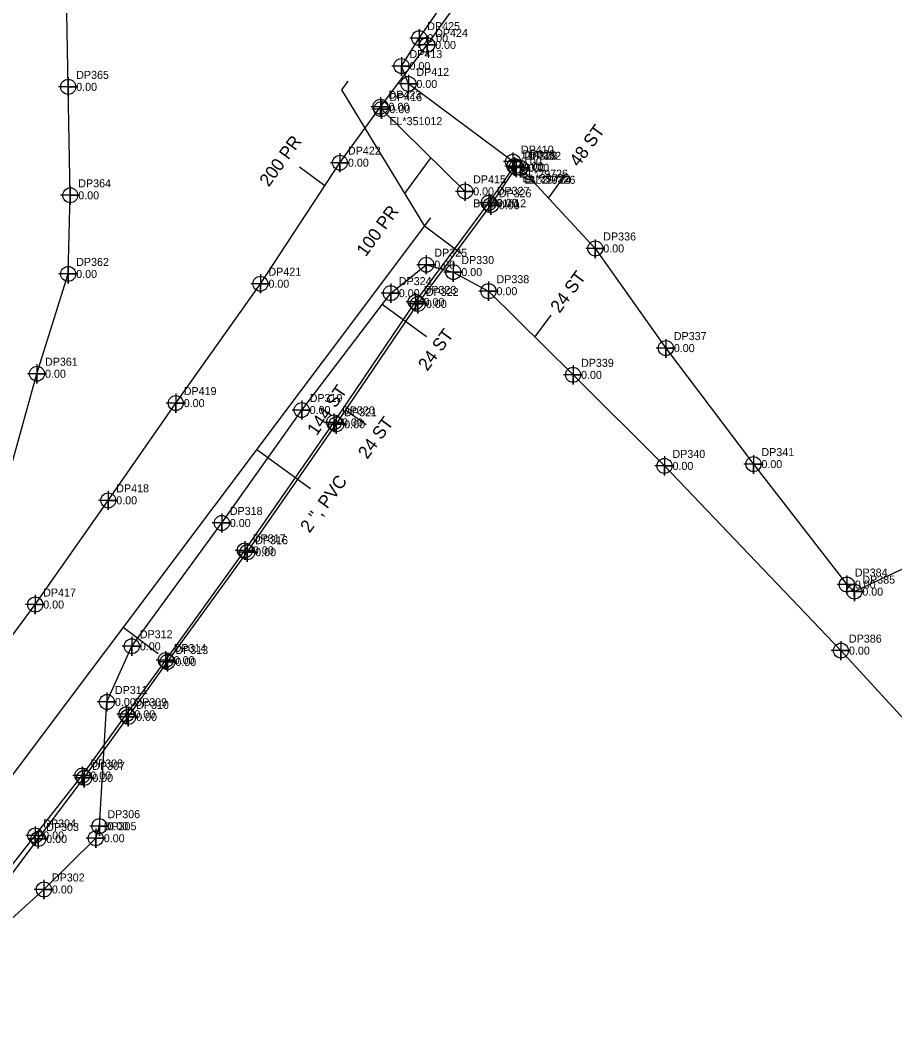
# Model space of a CAD drawing. Extents: x 1182504 to 1186036, y 573002 to 575111.
# Drawn here: x 1183867 to 1184140, y 573034.4 to 573350.5 of the extents above; entities that cross this region are included whole.
import ezdxf

# ---------------------------------------------------------------- set-up
doc = ezdxf.new("R2010")
doc.units = 0
for name, color, linetype in [('Exist Utilities Telephone UG Cable SUE LOS C', 7, 'Continuous'), ('Exist Utilities Telephone UG Cable SUE LOS C Cogo Comment', 7, 'Continuous'), ('Exist Utilities Telephone UG Cable SUE LOS C Cogo Elevation', 7, 'Continuous'), ('Exist Utilities Telephone UG Cable SUE LOS C Cogo Number', 7, 'Continuous'), ('Exist Utilities Telephone UG Cable SUE LOS C Cogo Point CELL', 7, 'Continuous'), ('Exist Utilities Telephone UG Cable SUE LOS C Leader', 7, 'Continuous'), ('Exist Utilities Telephone UG Cable SUE LOS C Text', 7, 'Continuous'), ('Exist Utilities Telephone UG Conduit SUE LOS B', 7, 'Continuous'), ('Exist Utilities Telephone UG Conduit SUE LOS B Cogo Comment', 7, 'Continuous'), ('Exist Utilities Telephone UG Conduit SUE LOS B Cogo Elevation', 7, 'Continuous'), ('Exist Utilities Telephone UG Conduit SUE LOS B Cogo Number', 7, 'Continuous'), ('Exist Utilities Telephone UG Conduit SUE LOS B Cogo Point CELL', 7, 'Continuous'), ('Exist Utilities Telephone UG Conduit SUE LOS B Leader', 7, 'Continuous'), ('Exist Utilities Telephone UG Conduit SUE LOS B Text', 7, 'Continuous'), ('Exist Utilities Telephone UG FO SUE LOS C', 7, 'Continuous'), ('Exist Utilities Telephone UG FO SUE LOS C Cogo Elevation', 7, 'Continuous'), ('Exist Utilities Telephone UG FO SUE LOS C Cogo Number', 7, 'Continuous'), ('Exist Utilities Telephone UG FO SUE LOS C Cogo Point CELL', 7, 'Continuous'), ('Exist Utilities Telephone UG FO SUE LOS C Leader', 7, 'Continuous'), ('Exist Utilities Telephone UG FO SUE LOS C Text', 7, 'Continuous'), ('Exist Utilities Water UG Line SUE LOS C', 7, 'Continuous'), ('Exist Utilities Water UG Line SUE LOS C Leader', 7, 'Continuous'), ('Exist Utilities Water UG Line SUE LOS C Text', 7, 'Continuous')]:
    doc.layers.add(name, color=color, linetype=linetype)

msp = doc.modelspace()

# ---------------------------------------------------------------- linework, layer by layer
at = {"layer": 'Exist Utilities Telephone UG Cable SUE LOS C'}
msp.add_line((1184005.86, 573297.12), (1183979.7, 573322.79), dxfattribs=at)
msp.add_lwpolyline([(1183761.25, 573038.53), (1183769.09, 573034.41), (1183772.83, 573037.9), (1183792.84, 573062.44), (1183815.5, 573091.52), (1183842.15, 573128.3), (1183871.65, 573168.11), (1183894.45, 573200.64), (1183915.52, 573231.01), (1183941.95, 573268.28), (1183966.78, 573306.07), (1183979.43, 573323.54), (1183993.99, 573342.83), (1184020.65, 573379.96), (1184047.47, 573417.15), (1184074.68, 573455.3), (1184101.33, 573490.9), (1184089.43, 573505.28)], dxfattribs=at)
at = {"layer": 'Exist Utilities Telephone UG Cable SUE LOS C Cogo Point CELL'}
for points in [[(1183993.99, 573345.83), (1183993.99, 573339.83), (1183993.99, 573342.83), (1183996.99, 573342.83), (1183990.99, 573342.83)], [(1183979.43, 573326.54), (1183979.43, 573320.54), (1183979.43, 573323.54), (1183982.43, 573323.54), (1183976.43, 573323.54)], [(1183979.7, 573325.79), (1183979.7, 573319.79), (1183979.7, 573322.79), (1183982.7, 573322.79), (1183976.7, 573322.79)], [(1183966.78, 573309.07), (1183966.78, 573303.07), (1183966.78, 573306.07), (1183969.78, 573306.07), (1183963.78, 573306.07)], [(1184005.86, 573300.12), (1184005.86, 573294.12), (1184005.86, 573297.12), (1184008.86, 573297.12), (1184002.86, 573297.12)], [(1183941.95, 573271.28), (1183941.95, 573265.28), (1183941.95, 573268.28), (1183944.95, 573268.28), (1183938.95, 573268.28)], [(1183915.52, 573234.01), (1183915.52, 573228.01), (1183915.52, 573231.01), (1183918.52, 573231.01), (1183912.52, 573231.01)], [(1183894.45, 573203.64), (1183894.45, 573197.64), (1183894.45, 573200.64), (1183897.45, 573200.64), (1183891.45, 573200.64)], [(1183871.65, 573171.11), (1183871.65, 573165.11), (1183871.65, 573168.11), (1183874.65, 573168.11), (1183868.65, 573168.11)]]:
    msp.add_lwpolyline(points, dxfattribs=at)
for centre in [(1183993.99, 573342.83), (1183979.43, 573323.54), (1183979.7, 573322.79), (1183966.78, 573306.07), (1184005.86, 573297.12), (1183941.95, 573268.28), (1183915.52, 573231.01), (1183894.45, 573200.64), (1183871.65, 573168.11)]:
    msp.add_circle(centre, 2.34, dxfattribs=at)
at = {"layer": 'Exist Utilities Telephone UG Cable SUE LOS C Leader'}
for p, q in [((1183995.14, 573307.64), (1183986.97, 573296.43)), ((1183962.06, 573298.88), (1183954.13, 573304.66))]:
    msp.add_line(p, q, dxfattribs=at)
at = {"layer": 'Exist Utilities Telephone UG Conduit SUE LOS B'}
for points in [[(1184020.78, 573306.4), (1183988.14, 573330.66), (1183985.98, 573336.24), (1183991.53, 573344.95), (1184017.37, 573382.34), (1184043.22, 573419.6), (1184071.03, 573458.88), (1184092.18, 573492.71), (1184101.38, 573521.29), (1184118.41, 573555.81), (1184137.37, 573593.76), (1184158.33, 573627.01), (1184186.36, 573674.25), (1184210.73, 573715)], [(1183829.51, 573041.35), (1183847.15, 573064.74), (1183871.66, 573096.02), (1183886.35, 573114.73), (1183900.1, 573133.86), (1183912.38, 573150.76), (1183937.09, 573185.03), (1183964.91, 573224.98), (1183990.4, 573262.6), (1184013.24, 573293.53), (1184021.26, 573304.97)], [(1183829.66, 573040.59), (1183848.87, 573063.35), (1183872.59, 573094.91), (1183886.95, 573113.99), (1183900.66, 573133.04), (1183912.9, 573150.17), (1183937.83, 573184.45), (1183965.61, 573224.4), (1183991.1, 573261.97), (1184013.84, 573292.77), (1184021.83, 573304.52)], [(1184023.09, 573304.47), (1184046.48, 573279.29), (1184068.5, 573248.18), (1184095.84, 573211.96), (1184125, 573174.35), (1184127.35, 573172.14), (1184149.57, 573182.55), (1184175.23, 573190.42), (1184203.21, 573208.51), (1184229.13, 573225.39)]]:
    msp.add_lwpolyline(points, dxfattribs=at)
at = {"layer": 'Exist Utilities Telephone UG Conduit SUE LOS B Cogo Point CELL'}
for points in [[(1183991.51, 573347.76), (1183991.55, 573341.95), (1183991.53, 573344.95), (1183994.55, 573344.95), (1183988.55, 573344.95)], [(1183985.96, 573339.06), (1183985.99, 573333.24), (1183985.98, 573336.24), (1183988.99, 573336.24), (1183982.99, 573336.24)], [(1183988.13, 573333.47), (1183988.16, 573327.66), (1183988.14, 573330.66), (1183991.16, 573330.66), (1183985.16, 573330.66)], [(1184020.76, 573309.22), (1184020.8, 573303.4), (1184020.78, 573306.4), (1184023.8, 573306.4), (1184017.8, 573306.4)], [(1184021.24, 573307.78), (1184021.27, 573301.97), (1184021.26, 573304.97), (1184024.27, 573304.97), (1184018.27, 573304.97)], [(1184021.81, 573307.34), (1184021.84, 573301.52), (1184021.83, 573304.52), (1184024.84, 573304.52), (1184018.84, 573304.52)], [(1184023.08, 573307.29), (1184023.11, 573301.47), (1184023.09, 573304.47), (1184026.11, 573304.47), (1184020.11, 573304.47)], [(1184013.22, 573296.34), (1184013.25, 573290.53), (1184013.24, 573293.53), (1184016.25, 573293.53), (1184010.25, 573293.53)], [(1184013.82, 573295.59), (1184013.86, 573289.77), (1184013.84, 573292.77), (1184016.86, 573292.77), (1184010.86, 573292.77)], [(1184046.46, 573282.1), (1184046.5, 573276.29), (1184046.48, 573279.29), (1184049.5, 573279.29), (1184043.5, 573279.29)], [(1183990.38, 573265.42), (1183990.41, 573259.6), (1183990.4, 573262.6), (1183993.41, 573262.6), (1183987.41, 573262.6)], [(1183991.08, 573264.79), (1183991.11, 573258.97), (1183991.1, 573261.97), (1183994.11, 573261.97), (1183988.11, 573261.97)], [(1184068.49, 573251), (1184068.52, 573245.18), (1184068.5, 573248.18), (1184071.52, 573248.18), (1184065.52, 573248.18)], [(1183964.9, 573227.8), (1183964.93, 573221.98), (1183964.91, 573224.98), (1183967.93, 573224.98), (1183961.93, 573224.98)], [(1183965.6, 573227.21), (1183965.63, 573221.4), (1183965.61, 573224.4), (1183968.63, 573224.4), (1183962.63, 573224.4)], [(1184095.83, 573214.77), (1184095.86, 573208.96), (1184095.84, 573211.96), (1184098.86, 573211.96), (1184092.86, 573211.96)], [(1183937.07, 573187.85), (1183937.11, 573182.03), (1183937.09, 573185.03), (1183940.11, 573185.03), (1183934.11, 573185.03)], [(1183937.81, 573187.27), (1183937.85, 573181.45), (1183937.83, 573184.45), (1183940.85, 573184.45), (1183934.85, 573184.45)], [(1184124.98, 573177.17), (1184125.01, 573171.35), (1184125, 573174.35), (1184128.01, 573174.35), (1184122.01, 573174.35)], [(1184127.33, 573174.95), (1184127.37, 573169.14), (1184127.35, 573172.14), (1184130.37, 573172.14), (1184124.37, 573172.14)], [(1183912.37, 573153.58), (1183912.4, 573147.76), (1183912.38, 573150.76), (1183915.4, 573150.76), (1183909.4, 573150.76)], [(1183912.88, 573152.99), (1183912.91, 573147.17), (1183912.9, 573150.17), (1183915.91, 573150.17), (1183909.91, 573150.17)], [(1183900.08, 573136.67), (1183900.11, 573130.86), (1183900.1, 573133.86), (1183903.11, 573133.86), (1183897.11, 573133.86)], [(1183900.65, 573135.85), (1183900.68, 573130.04), (1183900.66, 573133.04), (1183903.68, 573133.04), (1183897.68, 573133.04)], [(1183886.34, 573117.55), (1183886.37, 573111.73), (1183886.35, 573114.73), (1183889.37, 573114.73), (1183883.37, 573114.73)], [(1183886.93, 573116.81), (1183886.96, 573110.99), (1183886.95, 573113.99), (1183889.96, 573113.99), (1183883.96, 573113.99)], [(1183871.65, 573098.83), (1183871.68, 573093.02), (1183871.66, 573096.02), (1183874.68, 573096.02), (1183868.68, 573096.02)], [(1183872.57, 573097.73), (1183872.6, 573091.91), (1183872.59, 573094.91), (1183875.6, 573094.91), (1183869.6, 573094.91)]]:
    msp.add_lwpolyline(points, dxfattribs=at)
for centre in [(1183991.55, 573344.95), (1183985.99, 573336.24), (1183988.16, 573330.66), (1184020.8, 573306.4), (1184021.27, 573304.97), (1184021.84, 573304.52), (1184023.11, 573304.47), (1184013.25, 573293.53), (1184013.86, 573292.77), (1184046.5, 573279.29), (1183990.41, 573262.6), (1183991.11, 573261.97), (1184068.52, 573248.18), (1183964.93, 573224.98), (1183965.63, 573224.4), (1184095.86, 573211.96), (1183937.11, 573185.03), (1183937.85, 573184.45), (1184125.01, 573174.35), (1184127.37, 573172.14), (1183912.4, 573150.76), (1183912.91, 573150.17), (1183900.11, 573133.86), (1183900.68, 573133.04), (1183886.37, 573114.73), (1183886.96, 573113.99), (1183871.68, 573096.02), (1183872.6, 573094.91)]:
    msp.add_circle(centre, 2.34, dxfattribs=at)
at = {"layer": 'Exist Utilities Telephone UG Conduit SUE LOS B Leader'}
for p, q in [((1184031.9, 573294.99), (1184037.34, 573302.46)), ((1183968.63, 573228.85), (1183974.92, 573224.37))]:
    msp.add_line(p, q, dxfattribs=at)
at = {"layer": 'Exist Utilities Telephone UG FO SUE LOS C'}
for points in [[(1183831.2, 573051.4), (1183831.99, 573067.67), (1183835.94, 573100.34), (1183843.81, 573135.41), (1183849.42, 573158.28), (1183872.21, 573240.17), (1183881.95, 573271.33), (1183882.59, 573295.88), (1183881.95, 573329.75), (1183881.17, 573370.19), (1183880.74, 573416.08), (1183881.11, 573461.73), (1183880.38, 573505.49), (1183880.23, 573552), (1183881.56, 573597.96), (1183880.77, 573642.04), (1183880.14, 573689.54)], [(1183833.03, 573049.72), (1183841.55, 573050.99), (1183852.69, 573059.54), (1183874.36, 573079.14), (1183890.55, 573095.13), (1183891.68, 573098.9), (1183894.04, 573137.68), (1183901.8, 573155.08), (1183929.9, 573193.57), (1183954.83, 573228.84), (1183982.65, 573265.33), (1183993.74, 573274.22), (1184002.17, 573271.91), (1184013.15, 573265.94), (1184039.54, 573239.83), (1184068.08, 573211.39), (1184123.17, 573153.72), (1184151.22, 573123.17)]]:
    msp.add_lwpolyline(points, dxfattribs=at)
at = {"layer": 'Exist Utilities Telephone UG FO SUE LOS C Cogo Point CELL'}
for points in [[(1183881.95, 573332.75), (1183881.95, 573326.75), (1183881.95, 573329.75), (1183884.95, 573329.75), (1183878.95, 573329.75)], [(1183882.59, 573298.88), (1183882.59, 573292.88), (1183882.59, 573295.88), (1183885.59, 573295.88), (1183879.59, 573295.88)], [(1183993.74, 573277.22), (1183993.74, 573271.22), (1183993.74, 573274.22), (1183996.74, 573274.22), (1183990.74, 573274.22)], [(1183881.95, 573274.33), (1183881.95, 573268.33), (1183881.95, 573271.33), (1183884.95, 573271.33), (1183878.95, 573271.33)], [(1184002.17, 573274.91), (1184002.17, 573268.91), (1184002.17, 573271.91), (1184005.17, 573271.91), (1183999.17, 573271.91)], [(1183982.65, 573268.33), (1183982.65, 573262.33), (1183982.65, 573265.33), (1183985.65, 573265.33), (1183979.65, 573265.33)], [(1184013.15, 573268.94), (1184013.15, 573262.94), (1184013.15, 573265.94), (1184016.15, 573265.94), (1184010.15, 573265.94)], [(1183872.21, 573243.17), (1183872.21, 573237.17), (1183872.21, 573240.17), (1183875.21, 573240.17), (1183869.21, 573240.17)], [(1184039.54, 573242.83), (1184039.54, 573236.83), (1184039.54, 573239.83), (1184042.54, 573239.83), (1184036.54, 573239.83)], [(1183954.83, 573231.84), (1183954.83, 573225.84), (1183954.83, 573228.84), (1183957.83, 573228.84), (1183951.83, 573228.84)], [(1184068.08, 573214.39), (1184068.08, 573208.39), (1184068.08, 573211.39), (1184071.08, 573211.39), (1184065.08, 573211.39)], [(1183929.9, 573196.57), (1183929.9, 573190.57), (1183929.9, 573193.57), (1183932.9, 573193.57), (1183926.9, 573193.57)], [(1183901.8, 573158.08), (1183901.8, 573152.08), (1183901.8, 573155.08), (1183904.8, 573155.08), (1183898.8, 573155.08)], [(1184123.17, 573156.72), (1184123.17, 573150.72), (1184123.17, 573153.72), (1184126.17, 573153.72), (1184120.17, 573153.72)], [(1183894.04, 573140.68), (1183894.04, 573134.68), (1183894.04, 573137.68), (1183897.04, 573137.68), (1183891.04, 573137.68)], [(1183891.68, 573101.9), (1183891.68, 573095.9), (1183891.68, 573098.9), (1183894.68, 573098.9), (1183888.68, 573098.9)], [(1183890.55, 573098.13), (1183890.55, 573092.13), (1183890.55, 573095.13), (1183893.55, 573095.13), (1183887.55, 573095.13)], [(1183874.36, 573082.14), (1183874.36, 573076.14), (1183874.36, 573079.14), (1183877.36, 573079.14), (1183871.36, 573079.14)]]:
    msp.add_lwpolyline(points, dxfattribs=at)
for centre in [(1183881.95, 573329.75), (1183882.59, 573295.88), (1183993.74, 573274.22), (1184002.17, 573271.91), (1183881.95, 573271.33), (1183982.65, 573265.33), (1184013.15, 573265.94), (1183872.21, 573240.17), (1184039.54, 573239.83), (1183954.83, 573228.84), (1184068.08, 573211.39), (1183929.9, 573193.57), (1183901.8, 573155.08), (1184123.17, 573153.72), (1183894.04, 573137.68), (1183891.68, 573098.9), (1183890.55, 573095.13), (1183874.36, 573079.14)]:
    msp.add_circle(centre, 2.34, dxfattribs=at)
at = {"layer": 'Exist Utilities Telephone UG FO SUE LOS C Leader'}
for p, q in [((1183980.01, 573261.87), (1183993.78, 573251.83)), ((1184027.65, 573251.59), (1184032.67, 573258.49))]:
    msp.add_line(p, q, dxfattribs=at)
at = {"layer": 'Exist Utilities Water UG Line SUE LOS C'}
for p, q in [((1183822.46, 573058.84), (1183995.12, 573288.87)), ((1184004.82, 573277.54), (1183993.17, 573286.28)), ((1183910.07, 573152.67), (1183899.08, 573160.92))]:
    msp.add_line(p, q, dxfattribs=at)
msp.add_lwpolyline([(1183969.2, 573331.54), (1183967.23, 573328.83), (1183993.17, 573286.28)], dxfattribs=at)
at = {"layer": 'Exist Utilities Water UG Line SUE LOS C Leader'}
msp.add_line((1183940.83, 573216.55), (1183957.63, 573204.3), dxfattribs=at)

# ---------------------------------------------------------------- texts
at = {"layer": 'Exist Utilities Telephone UG Cable SUE LOS C Cogo Comment'}
for s, p in [('EL*351012', (1183982.2, 573317.79)), ('BL*351012', (1184008.36, 573292.12))]:
    msp.add_text(s, height=2.5, dxfattribs=at).set_placement(p)
at = {"layer": 'Exist Utilities Telephone UG Cable SUE LOS C Cogo Elevation'}
for p in [(1183996.49, 573341.58), (1183981.93, 573322.29), (1183982.2, 573321.54), (1183969.28, 573304.82), (1184008.36, 573295.87), (1183944.45, 573267.03), (1183918.02, 573229.76), (1183896.95, 573199.39), (1183874.15, 573166.86)]:
    msp.add_text('0.00', height=2.5, dxfattribs=at).set_placement(p)
at = {"layer": 'Exist Utilities Telephone UG Cable SUE LOS C Cogo Number'}
for s, p in [('DP424', (1183996.49, 573345.33)), ('DP423', (1183981.93, 573326.04)), ('DP416', (1183982.2, 573325.29)), ('DP422', (1183969.28, 573308.57)), ('DP415', (1184008.36, 573299.62)), ('DP421', (1183944.45, 573270.78)), ('DP419', (1183918.02, 573233.51)), ('DP418', (1183896.95, 573203.14)), ('DP417', (1183874.15, 573170.61))]:
    msp.add_text(s, height=2.5, dxfattribs=at).set_placement(p)
at = {"layer": 'Exist Utilities Telephone UG Cable SUE LOS C Text'}
for s, p in [('200 PR', (1183944.55, 573298.3)), ('100 PR', (1183974.84, 573276.47))]:
    msp.add_text(s, height=4, rotation=53.9157, dxfattribs=at).set_placement(p)
at = {"layer": 'Exist Utilities Telephone UG Conduit SUE LOS B Cogo Comment'}
for s, p in [('BL*29726', (1184023.28, 573301.4)), ('EL*29722', (1184023.76, 573299.97)), ('EL*29724', (1184024.33, 573299.52)), ('BL*29726', (1184025.59, 573299.47))]:
    msp.add_text(s, height=2.5, dxfattribs=at).set_placement(p)
at = {"layer": 'Exist Utilities Telephone UG Conduit SUE LOS B Cogo Elevation'}
for p in [(1183994.03, 573343.7), (1183988.48, 573334.99), (1183990.64, 573329.41), (1184023.28, 573305.15), (1184023.76, 573303.72), (1184024.33, 573303.27), (1184025.59, 573303.22), (1184015.74, 573292.28), (1184016.34, 573291.52), (1184048.98, 573278.04), (1183992.9, 573261.35), (1183993.6, 573260.72), (1184071, 573246.93), (1183967.41, 573223.73), (1183968.11, 573223.15), (1184098.34, 573210.71), (1183939.59, 573183.78), (1183940.33, 573183.2), (1184127.5, 573173.1), (1184129.85, 573170.89), (1183914.88, 573149.51), (1183915.4, 573148.92), (1183902.6, 573132.61), (1183903.16, 573131.79), (1183888.85, 573113.48), (1183889.45, 573112.74), (1183874.16, 573094.77), (1183875.09, 573093.66)]:
    msp.add_text('0.00', height=2.5, dxfattribs=at).set_placement(p)
at = {"layer": 'Exist Utilities Telephone UG Conduit SUE LOS B Cogo Number'}
for s, p in [('DP425', (1183994.03, 573347.45)), ('DP413', (1183988.48, 573338.74)), ('DP412', (1183990.64, 573333.16)), ('DP410', (1184023.28, 573308.9)), ('DP328', (1184023.76, 573307.47)), ('DP329', (1184024.33, 573307.02)), ('DP332', (1184025.59, 573306.97)), ('DP327', (1184015.74, 573296.03)), ('DP326', (1184016.34, 573295.27)), ('DP336', (1184048.98, 573281.79)), ('DP323', (1183992.9, 573265.1)), ('DP322', (1183993.6, 573264.47)), ('DP337', (1184071, 573250.68)), ('DP320', (1183967.41, 573227.48)), ('DP321', (1183968.11, 573226.9)), ('DP341', (1184098.34, 573214.46)), ('DP317', (1183939.59, 573187.53)), ('DP316', (1183940.33, 573186.95)), ('DP384', (1184127.5, 573176.85)), ('DP385', (1184129.85, 573174.64)), ('DP314', (1183914.88, 573153.26)), ('DP313', (1183915.4, 573152.67)), ('DP309', (1183902.6, 573136.36)), ('DP310', (1183903.16, 573135.54)), ('DP308', (1183888.85, 573117.23)), ('DP307', (1183889.45, 573116.49)), ('DP304', (1183874.16, 573098.52)), ('DP303', (1183875.09, 573097.41))]:
    msp.add_text(s, height=2.5, dxfattribs=at).set_placement(p)
at = {"layer": 'Exist Utilities Telephone UG Conduit SUE LOS B Text'}
for s, rotation, p in [('48 ST', 53.9157, (1184041.29, 573304.53)), ('144 ST', 55.8857, (1183959.53, 573220.6)), ('24 ST', 53.9157, (1183975.3, 573213.28))]:
    msp.add_text(s, height=4, rotation=rotation, dxfattribs=at).set_placement(p)
at = {"layer": 'Exist Utilities Telephone UG FO SUE LOS C Cogo Elevation'}
for p in [(1183884.45, 573328.5), (1183885.09, 573294.63), (1183996.24, 573272.97), (1183884.45, 573270.08), (1184004.67, 573270.66), (1183985.15, 573264.08), (1184015.65, 573264.69), (1183874.71, 573238.92), (1184042.04, 573238.58), (1183957.33, 573227.59), (1184070.58, 573210.14), (1183932.4, 573192.32), (1183904.3, 573153.83), (1184125.67, 573152.47), (1183896.54, 573136.43), (1183894.18, 573097.65), (1183893.05, 573093.88), (1183876.86, 573077.89)]:
    msp.add_text('0.00', height=2.5, dxfattribs=at).set_placement(p)
at = {"layer": 'Exist Utilities Telephone UG FO SUE LOS C Cogo Number'}
for s, p in [('DP365', (1183884.45, 573332.25)), ('DP364', (1183885.09, 573298.38)), ('DP325', (1183996.24, 573276.72)), ('DP330', (1184004.67, 573274.41)), ('DP362', (1183884.45, 573273.83)), ('DP338', (1184015.65, 573268.44)), ('DP324', (1183985.15, 573267.83)), ('DP361', (1183874.71, 573242.67)), ('DP339', (1184042.04, 573242.33)), ('DP319', (1183957.33, 573231.34)), ('DP340', (1184070.58, 573213.89)), ('DP318', (1183932.4, 573196.07)), ('DP312', (1183904.3, 573157.58)), ('DP386', (1184125.67, 573156.22)), ('DP311', (1183896.54, 573140.18)), ('DP306', (1183894.18, 573101.4)), ('DP305', (1183893.05, 573097.63)), ('DP302', (1183876.86, 573081.64))]:
    msp.add_text(s, height=2.5, dxfattribs=at).set_placement(p)
at = {"layer": 'Exist Utilities Telephone UG FO SUE LOS C Text'}
for rotation, p in [(53.6096, (1184035.32, 573258.86)), (53.9157, (1183994.06, 573240.78))]:
    msp.add_text('24 ST', height=4, rotation=rotation, dxfattribs=at).set_placement(p)
at = {"layer": 'Exist Utilities Water UG Line SUE LOS C Text'}
msp.add_text('2 ", PVC', height=4, rotation=53.9157, dxfattribs=at).set_placement((1183957.27, 573190.23))

doc.saveas('drawing.dxf')
